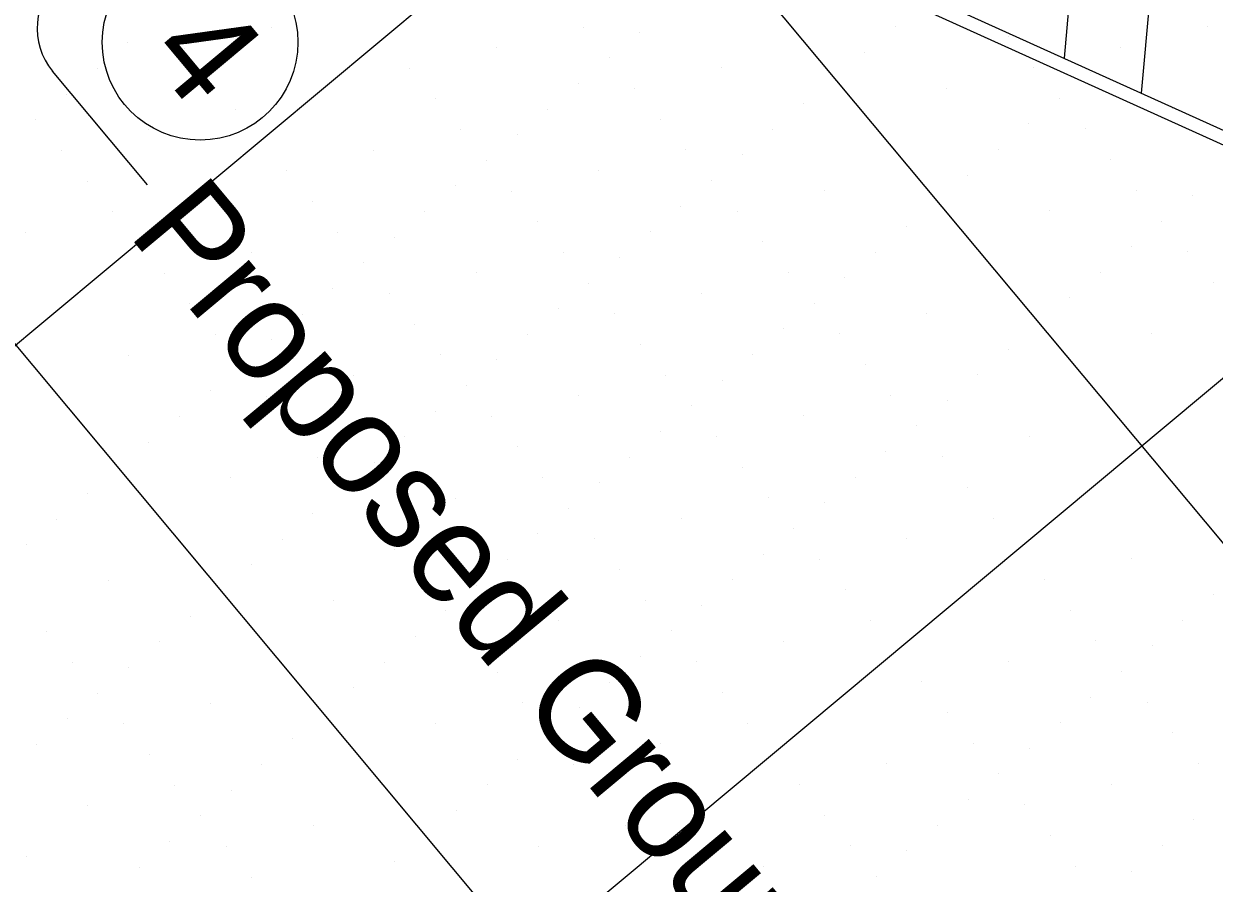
# Model space of a CAD drawing. Extents: x 2042995 to 2043795, y 305365 to 306249.
# Drawn here: x 2043359.03 to 2043388.81, y 305666.44 to 305687.94 of the extents above; entities that cross this region are included whole.
import ezdxf

# ---------------------------------------------------------------- set-up
doc = ezdxf.new("R2010")
doc.units = 0
for name, color, linetype in [('BR_AUTO DIMENSION', 7, 'Continuous'), ('BR_CONCRETE', 7, 'Continuous'), ('BR_GRID DOTS', 7, 'Continuous'), ('BR_GRID LINES', 7, 'Continuous'), ('BR_PRESTRESSED BEAM', 7, 'Continuous'), ('BR_TABLE LINES', 7, 'Continuous'), ('BR_TEXT', 7, 'Continuous')]:
    doc.layers.add(name, color=color, linetype=linetype)

msp = doc.modelspace()

# ---------------------------------------------------------------- linework, layer by layer
at = {"layer": 'BR_AUTO DIMENSION'}
msp.add_line((2043362.125, 305683.91), (2043359.755, 305686.748), dxfattribs=at)
msp.add_arc((2043361.034, 305687.816), 1.667, 129.8684, 219.8684, dxfattribs=at)
at = {"layer": 'BR_CONCRETE'}
for p, q in [((2043374.419, 305691.891), (2043417.993, 305672.168)), ((2043374.472, 305691.501), (2043417.786, 305671.896))]:
    msp.add_line(p, q, dxfattribs=at)
for points in [[(2043139.109, 306017.548), (2043148.199, 306007.16), (2043160.233, 305993.368), (2043172.245, 305979.557), (2043184.234, 305965.727), (2043196.201, 305951.879), (2043208.145, 305938.012), (2043220.067, 305924.126), (2043231.966, 305910.221), (2043243.843, 305896.297), (2043255.698, 305882.355), (2043267.529, 305868.394), (2043279.339, 305854.414), (2043291.126, 305840.415), (2043302.89, 305826.398), (2043314.632, 305812.361), (2043326.352, 305798.306), (2043338.049, 305784.233), (2043349.724, 305770.14), (2043361.376, 305756.029), (2043373.005, 305741.899), (2043384.613, 305727.75), (2043396.197, 305713.582), (2043407.76, 305699.396), (2043419.299, 305685.191), (2043430.817, 305670.967), (2043442.311, 305656.724), (2043453.784, 305642.463), (2043465.234, 305628.182), (2043476.661, 305613.883), (2043488.066, 305599.566), (2043499.448, 305585.229), (2043510.808, 305570.874), (2043522.146, 305556.5), (2043533.461, 305542.107), (2043544.753, 305527.695), (2043547.219, 305524.543)], [(2043273.14, 305860.139), (2043278.86, 305853.362), (2043290.647, 305839.364), (2043302.411, 305825.346), (2043314.153, 305811.31), (2043325.873, 305797.255), (2043337.57, 305783.181), (2043349.245, 305769.089), (2043360.897, 305754.977), (2043372.526, 305740.847), (2043384.134, 305726.698), (2043395.718, 305712.531), (2043407.281, 305698.344), (2043418.82, 305684.139), (2043425.623, 305675.744)]]:
    msp.add_spline(points, degree=3, dxfattribs=at)
at = {"layer": 'BR_GRID DOTS'}
for p, q in [((2043365.224, 305687.844), (2043365.224, 305687.844)), ((2043373.034, 305687.852), (2043373.034, 305687.852)), ((2043374.443, 305687.726), (2043374.443, 305687.726)), ((2043380.845, 305687.861), (2043380.845, 305687.861)), ((2043383.662, 305687.608), (2043383.662, 305687.608)), ((2043388.655, 305687.87), (2043388.655, 305687.87)), ((2043361.639, 305687.456), (2043361.639, 305687.456)), ((2043363.048, 305687.329), (2043363.048, 305687.329)), ((2043370.858, 305687.338), (2043370.858, 305687.338)), ((2043386.479, 305687.355), (2043386.479, 305687.355)), ((2043373.675, 305687.085), (2043373.675, 305687.085)), ((2043380.077, 305687.22), (2043380.077, 305687.22)), ((2043360.872, 305686.815), (2043360.872, 305686.815)), ((2043368.682, 305686.823), (2043368.682, 305686.823)), ((2043376.492, 305686.832), (2043376.492, 305686.832)), ((2043384.303, 305686.841), (2043384.303, 305686.841)), ((2043385.711, 305686.714), (2043385.711, 305686.714)), ((2043363.689, 305686.562), (2043363.689, 305686.562)), ((2043372.908, 305686.444), (2043372.908, 305686.444)), ((2043379.309, 305686.579), (2043379.309, 305686.579)), ((2043360.104, 305686.174), (2043360.104, 305686.174)), ((2043374.316, 305686.317), (2043374.316, 305686.317)), ((2043382.127, 305686.326), (2043382.127, 305686.326)), ((2043369.323, 305686.056), (2043369.323, 305686.056)), ((2043372.14, 305685.803), (2043372.14, 305685.803)), ((2043378.542, 305685.938), (2043378.542, 305685.938)), ((2043384.944, 305686.073), (2043384.944, 305686.073)), ((2043387.761, 305685.82), (2043387.761, 305685.82)), ((2043359.337, 305685.533), (2043359.337, 305685.533)), ((2043364.33, 305685.794), (2043364.33, 305685.794)), ((2043374.957, 305685.55), (2043374.957, 305685.55)), ((2043362.154, 305685.28), (2043362.154, 305685.28)), ((2043369.964, 305685.288), (2043369.964, 305685.288)), ((2043377.774, 305685.297), (2043377.774, 305685.297)), ((2043384.176, 305685.432), (2043384.176, 305685.432)), ((2043385.585, 305685.305), (2043385.585, 305685.305)), ((2043371.373, 305685.162), (2043371.373, 305685.162)), ((2043359.978, 305684.765), (2043359.978, 305684.765)), ((2043367.788, 305684.774), (2043367.788, 305684.774)), ((2043375.598, 305684.782), (2043375.598, 305684.782)), ((2043377.007, 305684.656), (2043377.007, 305684.656)), ((2043383.409, 305684.791), (2043383.409, 305684.791)), ((2043370.605, 305684.521), (2043370.605, 305684.521)), ((2043386.226, 305684.538), (2043386.226, 305684.538)), ((2043365.612, 305684.259), (2043365.612, 305684.259)), ((2043373.422, 305684.268), (2043373.422, 305684.268)), ((2043376.239, 305684.015), (2043376.239, 305684.015)), ((2043382.641, 305684.15), (2043382.641, 305684.15)), ((2043360.619, 305683.998), (2043360.619, 305683.998)), ((2043369.838, 305683.88), (2043369.838, 305683.88)), ((2043371.246, 305683.753), (2043371.246, 305683.753)), ((2043379.057, 305683.762), (2043379.057, 305683.762)), ((2043386.867, 305683.77), (2043386.867, 305683.77)), ((2043366.253, 305683.492), (2043366.253, 305683.492)), ((2043381.874, 305683.509), (2043381.874, 305683.509)), ((2043388.275, 305683.644), (2043388.275, 305683.644)), ((2043361.26, 305683.23), (2043361.26, 305683.23)), ((2043369.07, 305683.239), (2043369.07, 305683.239)), ((2043375.472, 305683.374), (2043375.472, 305683.374)), ((2043376.88, 305683.247), (2043376.88, 305683.247)), ((2043384.691, 305683.256), (2043384.691, 305683.256)), ((2043371.887, 305682.986), (2043371.887, 305682.986)), ((2043381.106, 305682.868), (2043381.106, 305682.868)), ((2043387.508, 305683.003), (2043387.508, 305683.003)), ((2043359.084, 305682.716), (2043359.084, 305682.716)), ((2043366.894, 305682.724), (2043366.894, 305682.724)), ((2043368.303, 305682.598), (2043368.303, 305682.598)), ((2043374.704, 305682.733), (2043374.704, 305682.733)), ((2043377.521, 305682.48), (2043377.521, 305682.48)), ((2043380.339, 305682.227), (2043380.339, 305682.227)), ((2043386.74, 305682.362), (2043386.74, 305682.362)), ((2043388.149, 305682.235), (2043388.149, 305682.235)), ((2043364.718, 305682.21), (2043364.718, 305682.21)), ((2043367.535, 305681.957), (2043367.535, 305681.957)), ((2043372.528, 305682.218), (2043372.528, 305682.218)), ((2043373.937, 305682.092), (2043373.937, 305682.092)), ((2043362.542, 305681.695), (2043362.542, 305681.695)), ((2043370.352, 305681.704), (2043370.352, 305681.704)), ((2043378.163, 305681.712), (2043378.163, 305681.712)), ((2043385.973, 305681.721), (2043385.973, 305681.721)), ((2043373.169, 305681.451), (2043373.169, 305681.451)), ((2043379.571, 305681.586), (2043379.571, 305681.586)), ((2043388.79, 305681.468), (2043388.79, 305681.468)), ((2043366.768, 305681.316), (2043366.768, 305681.316)), ((2043368.176, 305681.189), (2043368.176, 305681.189)), ((2043375.986, 305681.198), (2043375.986, 305681.198)), ((2043385.205, 305681.08), (2043385.205, 305681.08)), ((2043363.183, 305680.928), (2043363.183, 305680.928)), ((2043372.402, 305680.81), (2043372.402, 305680.81)), ((2043378.804, 305680.945), (2043378.804, 305680.945)), ((2043366, 305680.675), (2043366, 305680.675)), ((2043373.81, 305680.683), (2043373.81, 305680.683)), ((2043381.621, 305680.692), (2043381.621, 305680.692)), ((2043363.824, 305680.16), (2043363.824, 305680.16)), ((2043368.817, 305680.422), (2043368.817, 305680.422)), ((2043371.634, 305680.169), (2043371.634, 305680.169)), ((2043378.036, 305680.304), (2043378.036, 305680.304)), ((2043379.445, 305680.177), (2043379.445, 305680.177)), ((2043384.438, 305680.439), (2043384.438, 305680.439)), ((2043387.255, 305680.186), (2043387.255, 305680.186)), ((2043365.233, 305680.034), (2043365.233, 305680.034)), ((2043374.451, 305679.916), (2043374.451, 305679.916)), ((2043361.648, 305679.646), (2043361.648, 305679.646)), ((2043369.458, 305679.654), (2043369.458, 305679.654)), ((2043377.268, 305679.663), (2043377.268, 305679.663)), ((2043383.67, 305679.798), (2043383.67, 305679.798)), ((2043364.465, 305679.393), (2043364.465, 305679.393)), ((2043370.867, 305679.528), (2043370.867, 305679.528)), ((2043380.086, 305679.41), (2043380.086, 305679.41)), ((2043367.282, 305679.14), (2043367.282, 305679.14)), ((2043375.092, 305679.148), (2043375.092, 305679.148)), ((2043376.501, 305679.022), (2043376.501, 305679.022)), ((2043382.903, 305679.157), (2043382.903, 305679.157)), ((2043363.698, 305678.752), (2043363.698, 305678.752)), ((2043370.099, 305678.887), (2043370.099, 305678.887)), ((2043365.106, 305678.625), (2043365.106, 305678.625)), ((2043372.916, 305678.634), (2043372.916, 305678.634)), ((2043375.733, 305678.381), (2043375.733, 305678.381)), ((2043380.727, 305678.642), (2043380.727, 305678.642)), ((2043382.135, 305678.516), (2043382.135, 305678.516)), ((2043362.93, 305678.111), (2043362.93, 305678.111)), ((2043369.332, 305678.246), (2043369.332, 305678.246)), ((2043370.74, 305678.119), (2043370.74, 305678.119)), ((2043378.551, 305678.128), (2043378.551, 305678.128)), ((2043365.747, 305677.858), (2043365.747, 305677.858)), ((2043381.368, 305677.875), (2043381.368, 305677.875)), ((2043362.163, 305677.47), (2043362.163, 305677.47)), ((2043368.564, 305677.605), (2043368.564, 305677.605)), ((2043374.966, 305677.74), (2043374.966, 305677.74)), ((2043376.374, 305677.613), (2043376.374, 305677.613)), ((2043384.185, 305677.622), (2043384.185, 305677.622)), ((2043371.381, 305677.352), (2043371.381, 305677.352)), ((2043380.6, 305677.234), (2043380.6, 305677.234)), ((2043366.388, 305677.09), (2043366.388, 305677.09)), ((2043367.797, 305676.964), (2043367.797, 305676.964)), ((2043374.198, 305677.099), (2043374.198, 305677.099)), ((2043382.009, 305677.107), (2043382.009, 305677.107)), ((2043361.395, 305676.829), (2043361.395, 305676.829)), ((2043364.212, 305676.576), (2043364.212, 305676.576)), ((2043372.022, 305676.584), (2043372.022, 305676.584)), ((2043377.016, 305676.846), (2043377.016, 305676.846)), ((2043379.833, 305676.593), (2043379.833, 305676.593)), ((2043367.029, 305676.323), (2043367.029, 305676.323)), ((2043373.431, 305676.458), (2043373.431, 305676.458)), ((2043382.65, 305676.34), (2043382.65, 305676.34)), ((2043360.627, 305676.188), (2043360.627, 305676.188)), ((2043369.846, 305676.07), (2043369.846, 305676.07)), ((2043377.657, 305676.078), (2043377.657, 305676.078)), ((2043366.262, 305675.682), (2043366.262, 305675.682)), ((2043372.663, 305675.817), (2043372.663, 305675.817)), ((2043379.065, 305675.952), (2043379.065, 305675.952)), ((2043359.86, 305675.546), (2043359.86, 305675.546)), ((2043367.67, 305675.555), (2043367.67, 305675.555)), ((2043375.48, 305675.564), (2043375.48, 305675.564)), ((2043383.291, 305675.572), (2043383.291, 305675.572)), ((2043371.896, 305675.176), (2043371.896, 305675.176)), ((2043378.298, 305675.311), (2043378.298, 305675.311)), ((2043359.092, 305674.905), (2043359.092, 305674.905)), ((2043365.494, 305675.041), (2043365.494, 305675.041)), ((2043368.311, 305674.788), (2043368.311, 305674.788)), ((2043373.304, 305675.049), (2043373.304, 305675.049)), ((2043381.115, 305675.058), (2043381.115, 305675.058)), ((2043371.128, 305674.535), (2043371.128, 305674.535)), ((2043377.53, 305674.67), (2043377.53, 305674.67)), ((2043378.939, 305674.543), (2043378.939, 305674.543)), ((2043386.749, 305674.552), (2043386.749, 305674.552)), ((2043364.727, 305674.4), (2043364.727, 305674.4)), ((2043373.945, 305674.282), (2043373.945, 305674.282)), ((2043361.142, 305674.011), (2043361.142, 305674.011)), ((2043368.952, 305674.02), (2043368.952, 305674.02)), ((2043370.361, 305673.894), (2043370.361, 305673.894)), ((2043376.763, 305674.029), (2043376.763, 305674.029)), ((2043384.573, 305674.037), (2043384.573, 305674.037)), ((2043363.959, 305673.758), (2043363.959, 305673.758)), ((2043379.58, 305673.776), (2043379.58, 305673.776)), ((2043388.798, 305673.658), (2043388.798, 305673.658)), ((2043366.776, 305673.505), (2043366.776, 305673.505)), ((2043374.586, 305673.514), (2043374.586, 305673.514)), ((2043375.995, 305673.388), (2043375.995, 305673.388)), ((2043363.192, 305673.117), (2043363.192, 305673.117)), ((2043369.593, 305673.253), (2043369.593, 305673.253)), ((2043372.41, 305673), (2043372.41, 305673)), ((2043380.221, 305673.008), (2043380.221, 305673.008)), ((2043385.214, 305673.27), (2043385.214, 305673.27)), ((2043388.031, 305673.017), (2043388.031, 305673.017)), ((2043359.607, 305672.729), (2043359.607, 305672.729)), ((2043375.227, 305672.747), (2043375.227, 305672.747)), ((2043362.424, 305672.476), (2043362.424, 305672.476)), ((2043368.826, 305672.611), (2043368.826, 305672.611)), ((2043370.234, 305672.485), (2043370.234, 305672.485)), ((2043378.045, 305672.494), (2043378.045, 305672.494)), ((2043385.855, 305672.502), (2043385.855, 305672.502)), ((2043374.46, 305672.106), (2043374.46, 305672.106)), ((2043387.263, 305672.376), (2043387.263, 305672.376)), ((2043360.248, 305671.962), (2043360.248, 305671.962)), ((2043361.657, 305671.835), (2043361.657, 305671.835)), ((2043368.058, 305671.97), (2043368.058, 305671.97)), ((2043375.869, 305671.979), (2043375.869, 305671.979)), ((2043383.679, 305671.988), (2043383.679, 305671.988)), ((2043370.875, 305671.717), (2043370.875, 305671.717)), ((2043386.496, 305671.735), (2043386.496, 305671.735)), ((2043367.291, 305671.329), (2043367.291, 305671.329)), ((2043373.692, 305671.464), (2043373.692, 305671.464)), ((2043376.51, 305671.211), (2043376.51, 305671.211)), ((2043381.503, 305671.473), (2043381.503, 305671.473)), ((2043360.889, 305671.194), (2043360.889, 305671.194)), ((2043363.706, 305670.941), (2043363.706, 305670.941)), ((2043371.516, 305670.95), (2043371.516, 305670.95)), ((2043385.728, 305671.094), (2043385.728, 305671.094)), ((2043387.137, 305670.967), (2043387.137, 305670.967)), ((2043366.523, 305670.688), (2043366.523, 305670.688)), ((2043372.925, 305670.823), (2043372.925, 305670.823)), ((2043382.144, 305670.706), (2043382.144, 305670.706)), ((2043360.122, 305670.553), (2043360.122, 305670.553)), ((2043361.53, 305670.427), (2043361.53, 305670.427)), ((2043369.34, 305670.435), (2043369.34, 305670.435)), ((2043377.151, 305670.444), (2043377.151, 305670.444)), ((2043384.961, 305670.453), (2043384.961, 305670.453)), ((2043365.756, 305670.047), (2043365.756, 305670.047)), ((2043372.157, 305670.182), (2043372.157, 305670.182)), ((2043387.778, 305670.2), (2043387.778, 305670.2)), ((2043359.354, 305669.912), (2043359.354, 305669.912)), ((2043374.974, 305669.929), (2043374.974, 305669.929)), ((2043382.785, 305669.938), (2043382.785, 305669.938)), ((2043384.193, 305669.812), (2043384.193, 305669.812)), ((2043362.171, 305669.659), (2043362.171, 305669.659)), ((2043371.39, 305669.541), (2043371.39, 305669.541)), ((2043380.609, 305669.423), (2043380.609, 305669.423)), ((2043388.419, 305669.432), (2043388.419, 305669.432)), ((2043364.988, 305669.406), (2043364.988, 305669.406)), ((2043372.798, 305669.415), (2043372.798, 305669.415)), ((2043383.426, 305669.17), (2043383.426, 305669.17)), ((2043362.812, 305668.892), (2043362.812, 305668.892)), ((2043370.622, 305668.9), (2043370.622, 305668.9)), ((2043378.433, 305668.909), (2043378.433, 305668.909)), ((2043386.243, 305668.917), (2043386.243, 305668.917)), ((2043364.221, 305668.765), (2043364.221, 305668.765)), ((2043373.439, 305668.647), (2043373.439, 305668.647)), ((2043382.658, 305668.529), (2043382.658, 305668.529)), ((2043360.636, 305668.377), (2043360.636, 305668.377)), ((2043369.855, 305668.259), (2043369.855, 305668.259)), ((2043384.067, 305668.403), (2043384.067, 305668.403)), ((2043363.453, 305668.124), (2043363.453, 305668.124)), ((2043379.074, 305668.141), (2043379.074, 305668.141)), ((2043388.292, 305668.023), (2043388.292, 305668.023)), ((2043366.27, 305667.871), (2043366.27, 305667.871)), ((2043374.08, 305667.88), (2043374.08, 305667.88)), ((2043381.891, 305667.888), (2043381.891, 305667.888)), ((2043384.708, 305667.635), (2043384.708, 305667.635)), ((2043362.686, 305667.483), (2043362.686, 305667.483)), ((2043364.094, 305667.357), (2043364.094, 305667.357)), ((2043369.087, 305667.618), (2043369.087, 305667.618)), ((2043371.904, 305667.365), (2043371.904, 305667.365)), ((2043379.715, 305667.374), (2043379.715, 305667.374)), ((2043387.525, 305667.382), (2043387.525, 305667.382)), ((2043359.101, 305667.095), (2043359.101, 305667.095)), ((2043381.123, 305667.247), (2043381.123, 305667.247)), ((2043361.918, 305666.842), (2043361.918, 305666.842)), ((2043368.32, 305666.977), (2043368.32, 305666.977)), ((2043377.539, 305666.859), (2043377.539, 305666.859)), ((2043385.349, 305666.868), (2043385.349, 305666.868)), ((2043386.757, 305666.741), (2043386.757, 305666.741)), ((2043364.735, 305666.589), (2043364.735, 305666.589)), ((2043380.356, 305666.606), (2043380.356, 305666.606))]:
    msp.add_line(p, q, dxfattribs=at)
at = {"layer": 'BR_GRID LINES'}
for p, q in [((2043194.694, 305907.624), (2043538.711, 305495.723)), ((2043179.344, 305894.804), (2043523.36, 305482.903)), ((2043450.933, 305756.822), (2043297.429, 305628.617)), ((2043463.754, 305741.471), (2043310.25, 305613.266))]:
    msp.add_line(p, q, dxfattribs=at)
at = {"layer": 'BR_PRESTRESSED BEAM'}
msp.add_spline([(2043269.336, 305856.962), (2043274.734, 305850.568), (2043286.521, 305836.569), (2043298.285, 305822.551), (2043310.027, 305808.515), (2043321.747, 305794.46), (2043333.444, 305780.386), (2043345.119, 305766.294), (2043356.771, 305752.183), (2043368.4, 305738.053), (2043380.007, 305723.904), (2043391.592, 305709.736), (2043403.154, 305695.55), (2043414.694, 305681.345), (2043421.811, 305672.561)], degree=3, dxfattribs=at)
at = {"layer": 'BR_TABLE LINES'}
for p, q in [((2043387.373, 305712.811), (2043385.061, 305687.074)), ((2043389.343, 305712.392), (2043386.991, 305686.201))]:
    msp.add_line(p, q, dxfattribs=at)
at = {"layer": 'BR_TEXT'}
msp.add_circle((2043363.444, 305687.473), 2.447, dxfattribs=at)

# ---------------------------------------------------------------- texts
for s, p in [('4', (2043362.067, 305687.159)), ('Proposed Ground (Typ.)', (2043361.617, 305682.681))]:
    msp.add_text(s, height=2.5, rotation=309.8684, dxfattribs=at).set_placement(p)

doc.saveas('drawing.dxf')
